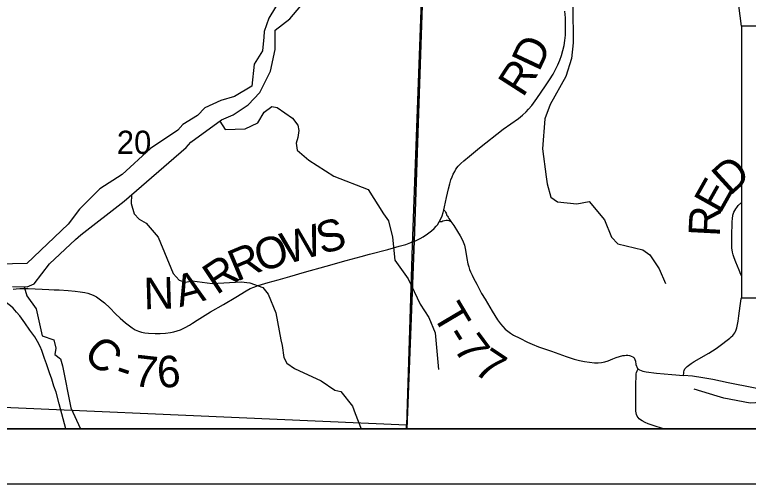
# Model space of a CAD drawing. Extents: x 0 to 34, y 0 to 22.
# Drawn here: x 25.417 to 26.74, y 14 to 14.847 of the extents above; entities that cross this region are included whole.
import ezdxf

# ---------------------------------------------------------------- set-up
doc = ezdxf.new("R2010")
doc.units = 0
for name, color, linetype in [('GM_X_Adjacent_County', 7, 'Continuous'), ('GM_X_County', 7, 'Continuous'), ('GM_X_County_Road', 7, 'Continuous'), ('GM_X_County_Road_Text', 7, 'Continuous'), ('GM_X_Minor_River', 7, 'Continuous'), ('GM_X_Section', 7, 'Continuous'), ('GM_X_Section_Text', 7, 'Continuous'), ('GM_X_Township', 7, 'Continuous'), ('GM_X_Township_Road', 7, 'Continuous'), ('GM_X_Township_Road_Text', 7, 'Continuous'), ('SH_Data', 7, 'Continuous'), ('SH_Text', 7, 'Continuous')]:
    doc.layers.add(name, color=color, linetype=linetype)

msp = doc.modelspace()

# ---------------------------------------------------------------- linework, layer by layer
at = {"layer": 'GM_X_Adjacent_County'}
msp.add_lwpolyline([(24.0167, 18.0693), (24.0167, 14.1), (30.8167, 14.1), (30.8167, 17.8174)], dxfattribs=at)
at = {"layer": 'GM_X_County'}
msp.add_lwpolyline([(24.0167, 18.0693), (24.0167, 14.1), (30.8167, 14.1), (30.8167, 17.8174)], dxfattribs=at)
at = {"layer": 'GM_X_County_Road'}
for points in [[(26.1911, 14.4951), (26.1923, 14.5001), (26.1959, 14.5173), (26.1992, 14.5328), (26.2015, 14.5418), (26.2036, 14.5487), (26.2058, 14.5544), (26.208, 14.5592), (26.2105, 14.5639), (26.2127, 14.5679), (26.2167, 14.5735), (26.2215, 14.5785), (26.2272, 14.5834), (26.2371, 14.5917), (26.2553, 14.6068), (26.2982, 14.6402), (26.3253, 14.6596), (26.3326, 14.6653), (26.3394, 14.6716), (26.3437, 14.6761), (26.3495, 14.6832), (26.3586, 14.6958), (26.3745, 14.7187), (26.3814, 14.7291), (26.3878, 14.7396), (26.3922, 14.7478), (26.3963, 14.7562), (26.4001, 14.7646), (26.4033, 14.7733), (26.4058, 14.7822), (26.4078, 14.7912), (26.4092, 14.8004), (26.4101, 14.8096), (26.4106, 14.8221), (26.4106, 14.8317), (26.4102, 14.8408), (26.4093, 14.8532)], [(26.1826, 14.4732), (26.1854, 14.4786), (26.1879, 14.4843), (26.1899, 14.4901), (26.1911, 14.4951)], [(26.1357, 14.4375), (26.1374, 14.4382), (26.14, 14.4392), (26.1483, 14.4433), (26.1537, 14.4463), (26.1614, 14.4514), (26.1687, 14.457), (26.1733, 14.4611), (26.1774, 14.4656), (26.1793, 14.468), (26.1826, 14.4732)], [(25.4147, 14.352), (25.4201, 14.3525), (25.4263, 14.3532), (25.4325, 14.3533), (25.4418, 14.353), (25.4541, 14.3524), (25.4665, 14.3518), (25.4789, 14.3513), (25.4881, 14.3509), (25.4973, 14.3505), (25.5136, 14.3497), (25.5264, 14.3485), (25.5355, 14.3473), (25.5436, 14.3458), (25.5491, 14.3445), (25.5536, 14.3431), (25.559, 14.3412), (25.5649, 14.338), (25.5697, 14.3347), (25.5746, 14.3308), (25.579, 14.327), (25.5887, 14.3181), (25.5989, 14.3076), (25.6075, 14.2997), (25.6172, 14.2914), (25.6244, 14.2855), (25.6293, 14.2819), (25.6346, 14.2787), (25.6402, 14.2763), (25.6461, 14.2745), (25.6521, 14.2733), (25.6582, 14.2726), (25.6706, 14.272), (25.6798, 14.272), (25.6891, 14.2726), (25.6983, 14.2738), (25.7043, 14.275), (25.7103, 14.2766), (25.716, 14.2787), (25.7243, 14.2827), (25.7323, 14.287), (25.738, 14.2908), (25.7461, 14.2959), (25.7702, 14.3108), (25.7938, 14.3242), (25.8161, 14.3377), (25.8345, 14.3491), (25.8417, 14.353), (25.8482, 14.3557), (25.8565, 14.3584), (25.8744, 14.3638), (25.8922, 14.3689), (25.9131, 14.3748), (25.9399, 14.3826), (25.9788, 14.3936), (26.0147, 14.4036), (26.0417, 14.4109), (26.0567, 14.4149), (26.0897, 14.4236), (26.1107, 14.4292), (26.1223, 14.4326), (26.1314, 14.4357), (26.1357, 14.4375)], [(25.5093, 14.1), (25.5072, 14.1091), (25.4977, 14.1452), (25.4917, 14.166), (25.4878, 14.1769), (25.4839, 14.1895), (25.4802, 14.2008), (25.4748, 14.2174), (25.4712, 14.2269), (25.466, 14.2413), (25.4629, 14.2487), (25.4586, 14.2576), (25.4538, 14.2657), (25.4448, 14.2781), (25.4354, 14.2911), (25.4264, 14.3035), (25.4206, 14.3106), (25.4143, 14.3173), (25.4098, 14.3215), (25.4026, 14.3273), (25.3951, 14.3326), (25.3883, 14.3367), (25.3757, 14.343)]]:
    msp.add_lwpolyline(points, dxfattribs=at)
at = {"layer": 'GM_X_Minor_River'}
for points in [[(25.9015, 14.8837), (25.8756, 14.8407), (25.867, 14.8164), (25.8666, 14.8061), (25.8641, 14.7815), (25.849, 14.7575), (25.8447, 14.7177), (25.8133, 14.6989), (25.7887, 14.692), (25.7603, 14.6786), (25.7468, 14.6649), (25.7203, 14.6485), (25.7116, 14.6386), (25.6621, 14.6053), (25.6112, 14.5585), (25.5707, 14.5325), (25.5338, 14.4963), (25.5138, 14.4689), (25.4394, 14.3984), (25.3606, 14.3961)], [(25.4135, 14.3565), (25.4396, 14.3559), (25.4525, 14.3616), (25.48, 14.3978), (25.5268, 14.4416), (25.5366, 14.45), (25.6148, 14.5107), (25.7266, 14.6071), (25.7348, 14.617), (25.79, 14.6571), (25.8112, 14.6663), (25.838, 14.6842), (25.8595, 14.7067), (25.8783, 14.7451), (25.8868, 14.7842), (25.887, 14.8188), (25.9135, 14.8394), (25.9497, 14.8828)], [(26.4236, 14.862), (26.4242, 14.796), (26.421, 14.768), (26.4109, 14.7353), (26.3827, 14.6847), (26.373, 14.6589), (26.3687, 14.605), (26.3753, 14.5542), (26.3773, 14.542), (26.3838, 14.5178), (26.396, 14.5095), (26.4305, 14.5055), (26.4532, 14.5097), (26.4807, 14.4769), (26.4933, 14.4454), (26.5048, 14.4337), (26.5495, 14.4229), (26.5621, 14.4135), (26.5793, 14.3885), (26.5904, 14.362)], [(25.7869, 14.6549), (25.7965, 14.6397), (25.8325, 14.641), (25.8556, 14.6517), (25.8669, 14.6711), (25.8809, 14.6814), (25.8907, 14.6792), (25.9181, 14.6599), (25.9276, 14.6475), (25.9296, 14.638), (25.9277, 14.6255), (25.9248, 14.6148), (25.9263, 14.6027), (25.9473, 14.5846), (25.9925, 14.5555), (26.0544, 14.5315), (26.0823, 14.4876), (26.091, 14.4752), (26.0984, 14.4456), (26.1024, 14.4039), (26.1264, 14.3706), (26.1482, 14.3248), (26.1639, 14.301), (26.1754, 14.2733), (26.1813, 14.2073)], [(25.6277, 14.5218), (25.627, 14.5065), (25.6327, 14.4876), (25.6419, 14.4778), (25.6544, 14.471), (25.6757, 14.4457), (25.703, 14.3802), (25.7136, 14.3681), (25.725, 14.3647), (25.7375, 14.3667), (25.7735, 14.3623), (25.8258, 14.3648), (25.8414, 14.3633), (25.8646, 14.3547), (25.8745, 14.343), (25.8883, 14.3093), (25.8968, 14.2604), (25.8995, 14.2501), (25.9027, 14.2285), (25.908, 14.2183), (25.9217, 14.2089), (25.9696, 14.1863), (25.9947, 14.1697), (26.0053, 14.1671), (26.0262, 14.1407), (26.0312, 14.1278), (26.0421, 14.1)], [(25.4341, 14.356), (25.439, 14.3396), (25.4561, 14.3165), (25.4666, 14.268), (25.4875, 14.2605), (25.4913, 14.2453), (25.4895, 14.2343), (25.5001, 14.226), (25.5036, 14.2135), (25.5184, 14.1377), (25.5359, 14.1)], [(26.8747, 14.1), (26.8538, 14.1207), (26.8275, 14.1381), (26.7809, 14.1485), (26.7434, 14.1461), (26.6959, 14.1553), (26.6838, 14.1587), (26.6424, 14.1718)]]:
    msp.add_lwpolyline(points, dxfattribs=at)
at = {"layer": 'GM_X_Section'}
msp.add_line((25.1065, 14.1), (26.1234, 14.1), dxfattribs=at)
msp.add_lwpolyline([(25.1469, 15.1542), (26.1585, 15.1031), (26.1524, 14.9369), (26.1341, 14.4312), (26.1236, 14.1064), (25.1079, 14.1514)], close=True, dxfattribs=at)
msp.add_lwpolyline([(26.1234, 14.1), (26.1236, 14.1064), (25.1079, 14.1514), (25.1065, 14.1)], dxfattribs=at)
at = {"layer": 'GM_X_Township'}
msp.add_line((26.1244, 14.1), (30.0847, 14.1), dxfattribs=at)
for points in [[(24.0167, 18.0693), (24.0167, 14.1), (26.1244, 14.1)], [(26.2189, 16.9294), (26.2007, 16.3781), (26.2005, 16.374), (26.2005, 16.3538), (26.1991, 16.332), (26.1747, 15.5373), (26.1374, 14.4382), (26.1244, 14.1)], [(26.1244, 14.1), (26.1374, 14.4382), (26.1747, 15.5373), (26.1991, 16.332), (26.2005, 16.3538), (26.2005, 16.374), (26.2007, 16.3781), (26.2189, 16.9294)]]:
    msp.add_lwpolyline(points, dxfattribs=at)
at = {"layer": 'GM_X_Township_Road'}
for points in [[(26.7275, 14.3756), (26.7266, 14.3783), (26.7232, 14.3862), (26.7173, 14.4006), (26.7142, 14.4085), (26.7124, 14.414), (26.7112, 14.4186), (26.7103, 14.4264), (26.71, 14.4366), (26.7102, 14.4427), (26.7103, 14.4521), (26.7107, 14.4676), (26.7111, 14.4737), (26.7114, 14.4788), (26.7122, 14.4854), (26.7137, 14.4905), (26.7155, 14.4938), (26.7172, 14.4964), (26.7192, 14.4991), (26.7219, 14.5026), (26.7275, 14.5079)], [(26.1911, 14.4951), (26.193, 14.4928), (26.1941, 14.4909), (26.195, 14.4887), (26.1966, 14.4849), (26.1974, 14.4832), (26.1985, 14.4814), (26.1998, 14.4792), (26.2035, 14.4739)], [(26.1826, 14.4732), (26.1852, 14.4737), (26.1872, 14.4741), (26.1893, 14.4749), (26.192, 14.4758), (26.1951, 14.4761), (26.1976, 14.4762), (26.2, 14.4757), (26.2035, 14.4739)], [(26.2035, 14.4739), (26.2089, 14.4664), (26.2158, 14.4561), (26.2207, 14.4482), (26.2236, 14.4427), (26.2261, 14.4371), (26.2281, 14.4312), (26.2302, 14.4222), (26.2326, 14.4069), (26.2345, 14.3977), (26.2358, 14.392), (26.2372, 14.3876), (26.2388, 14.3829), (26.2418, 14.3771), (26.2447, 14.3718), (26.2502, 14.3606), (26.259, 14.3443), (26.2652, 14.3336), (26.2781, 14.3124), (26.288, 14.2968), (26.2934, 14.2892), (26.2973, 14.2844), (26.3016, 14.2799), (26.3062, 14.2759), (26.3113, 14.2723), (26.3167, 14.2692), (26.3277, 14.2635), (26.3416, 14.2565), (26.3501, 14.2526), (26.3617, 14.2481), (26.3851, 14.2398), (26.4115, 14.2304), (26.4262, 14.2256), (26.4353, 14.2233), (26.4444, 14.2214), (26.4536, 14.22), (26.4629, 14.2192), (26.4691, 14.2192), (26.4753, 14.2197), (26.4813, 14.2208), (26.4873, 14.2226), (26.4959, 14.2261), (26.5016, 14.2286), (26.5075, 14.2306), (26.5135, 14.232), (26.5166, 14.2325), (26.5197, 14.2328), (26.5228, 14.2327), (26.5258, 14.2322), (26.5273, 14.2319), (26.5288, 14.2313), (26.5316, 14.2299), (26.5328, 14.2289), (26.5339, 14.2279), (26.5348, 14.2267), (26.5355, 14.2252), (26.5364, 14.2222), (26.5374, 14.2161), (26.5381, 14.2131), (26.5387, 14.2116), (26.5395, 14.2103), (26.5403, 14.2091), (26.5415, 14.208)], [(26.623, 14.1963), (26.6234, 14.201), (26.6236, 14.2029), (26.6242, 14.2054), (26.6257, 14.208), (26.6275, 14.2103), (26.6296, 14.2124), (26.6319, 14.2144), (26.6369, 14.218), (26.6421, 14.2212), (26.6686, 14.2367), (26.6817, 14.2449), (26.6919, 14.252), (26.7018, 14.2596), (26.7066, 14.2637), (26.7093, 14.2659), (26.7118, 14.2683), (26.7138, 14.2708), (26.7156, 14.2731), (26.7171, 14.2758), (26.7182, 14.2787), (26.719, 14.2819), (26.7202, 14.2882), (26.7215, 14.2943), (26.7229, 14.3035), (26.7241, 14.3127), (26.7255, 14.322), (26.7273, 14.3342), (26.7277, 14.3361)], [(26.5872, 14.1), (26.5685, 14.1063), (26.5596, 14.1092), (26.5539, 14.1115), (26.5484, 14.1144), (26.5458, 14.1161), (26.5434, 14.1181), (26.5413, 14.1204), (26.5396, 14.123), (26.5384, 14.1258), (26.5376, 14.1288), (26.5372, 14.1319), (26.537, 14.1381), (26.5372, 14.1536), (26.5373, 14.1815), (26.5376, 14.194), (26.5377, 14.1972), (26.5379, 14.1993), (26.5383, 14.2014), (26.5396, 14.2047), (26.5415, 14.208)], [(26.5415, 14.208), (26.5425, 14.2071), (26.5439, 14.2062), (26.5468, 14.205), (26.5497, 14.2041), (26.5558, 14.2029), (26.5743, 14.2007), (26.6022, 14.1981), (26.623, 14.1963)], [(26.9166, 14.1), (26.9157, 14.1007), (26.9063, 14.1087), (26.8902, 14.1234), (26.8808, 14.1315), (26.8734, 14.1371), (26.8682, 14.1405), (26.8627, 14.1434), (26.8571, 14.1459), (26.8484, 14.1492), (26.8395, 14.1521), (26.8216, 14.1572), (26.7976, 14.1634), (26.7704, 14.1696), (26.7491, 14.1742), (26.7035, 14.1832), (26.6762, 14.1888), (26.6579, 14.1921), (26.6395, 14.1947), (26.623, 14.1963)]]:
    msp.add_lwpolyline(points, dxfattribs=at)
at = {"layer": 'SH_Data'}
for points in [[(23.9167, 21), (30.9167, 21), (30.9167, 14), (23.9167, 14)], [(24.0167, 20.9), (30.8167, 20.9), (30.8167, 14.1), (24.0167, 14.1)]]:
    msp.add_lwpolyline(points, close=True, dxfattribs=at)
at = {"layer": 'SH_Text'}
for points in [[(26.5011, 16.5809), (27.1585, 14.8261), (26.7275, 14.8261)], [(26.7275, 14.3361), (28.4085, 14.3361), (28.4085, 14.8261), (26.7275, 14.8261)]]:
    msp.add_lwpolyline(points, close=True, dxfattribs=at)

# ---------------------------------------------------------------- texts
at = {"layer": 'GM_X_County_Road_Text'}
for s, rotation, p in [('D', 64.8659, (26.3625, 14.7422)), ('R', 57.3773, (26.3335, 14.696)), ('S', 15.7528, (25.9702, 14.4143)), ('W', 15.7516, (25.9068, 14.3964)), ('O', 16.15, (25.8589, 14.3825)), ('R', 22.7763, (25.8175, 14.365)), ('R', 33.7316, (25.7812, 14.3405)), ('A', 15.1275, (25.7147, 14.3191)), ('N', 1.7232, (25.6504, 14.3155)), ('C', 318.5181, (25.5384, 14.231)), ('7', 353.5556, (25.6297, 14.1776)), ('6', 3.9675, (25.6757, 14.1735)), ('-', 341.6672, (25.595, 14.1877))]:
    msp.add_text(s, height=0.0568, rotation=rotation, dxfattribs=at).set_placement(p)
at = {"layer": 'GM_X_Section_Text'}
msp.add_text('20', height=0.04186, rotation=0, dxfattribs=at).set_placement((25.6013, 14.5957))
at = {"layer": 'GM_X_Township_Road_Text'}
for s, rotation, p in [('D', 42.3227, (26.7069, 14.519)), ('E', 60.624, (26.689, 14.4857)), ('R', 87.0442, (26.6885, 14.4457)), ('T', 300.6778, (26.1691, 14.306)), ('-', 302.0183, (26.1915, 14.2682)), ('7', 306.7331, (26.2067, 14.2443)), ('7', 326.1212, (26.2425, 14.2021))]:
    msp.add_text(s, height=0.0568, rotation=rotation, dxfattribs=at).set_placement(p)

doc.saveas('drawing.dxf')
